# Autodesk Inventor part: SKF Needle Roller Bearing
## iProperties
Company: jsm
Author: XMN5642
Shininess: 41.0
PropertySet Name: _Private Model Information
Created: 2001-04
Part Number: SKF Needle Roller Bearing
Document SubType Name: Modeling
Designer: XMN5642
Control State: 0
Master: False
Checked Out: False
PropertySet Name: Design Tracking Control
Density: 0.0
Volumn: 0.0
Area: 0.0
PropertySet Name: Model Information
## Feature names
1. Extrusion1
2. Extrusion2
3. Extrusion3
4. Extrusion4
5. Extrusion5
6. Extrusion6
7. Circular Pattern1
8. Chamfer1
9. Revolution1
